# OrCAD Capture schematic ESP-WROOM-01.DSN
size A3; title: ESP-WROOM-01; rev: 1.0
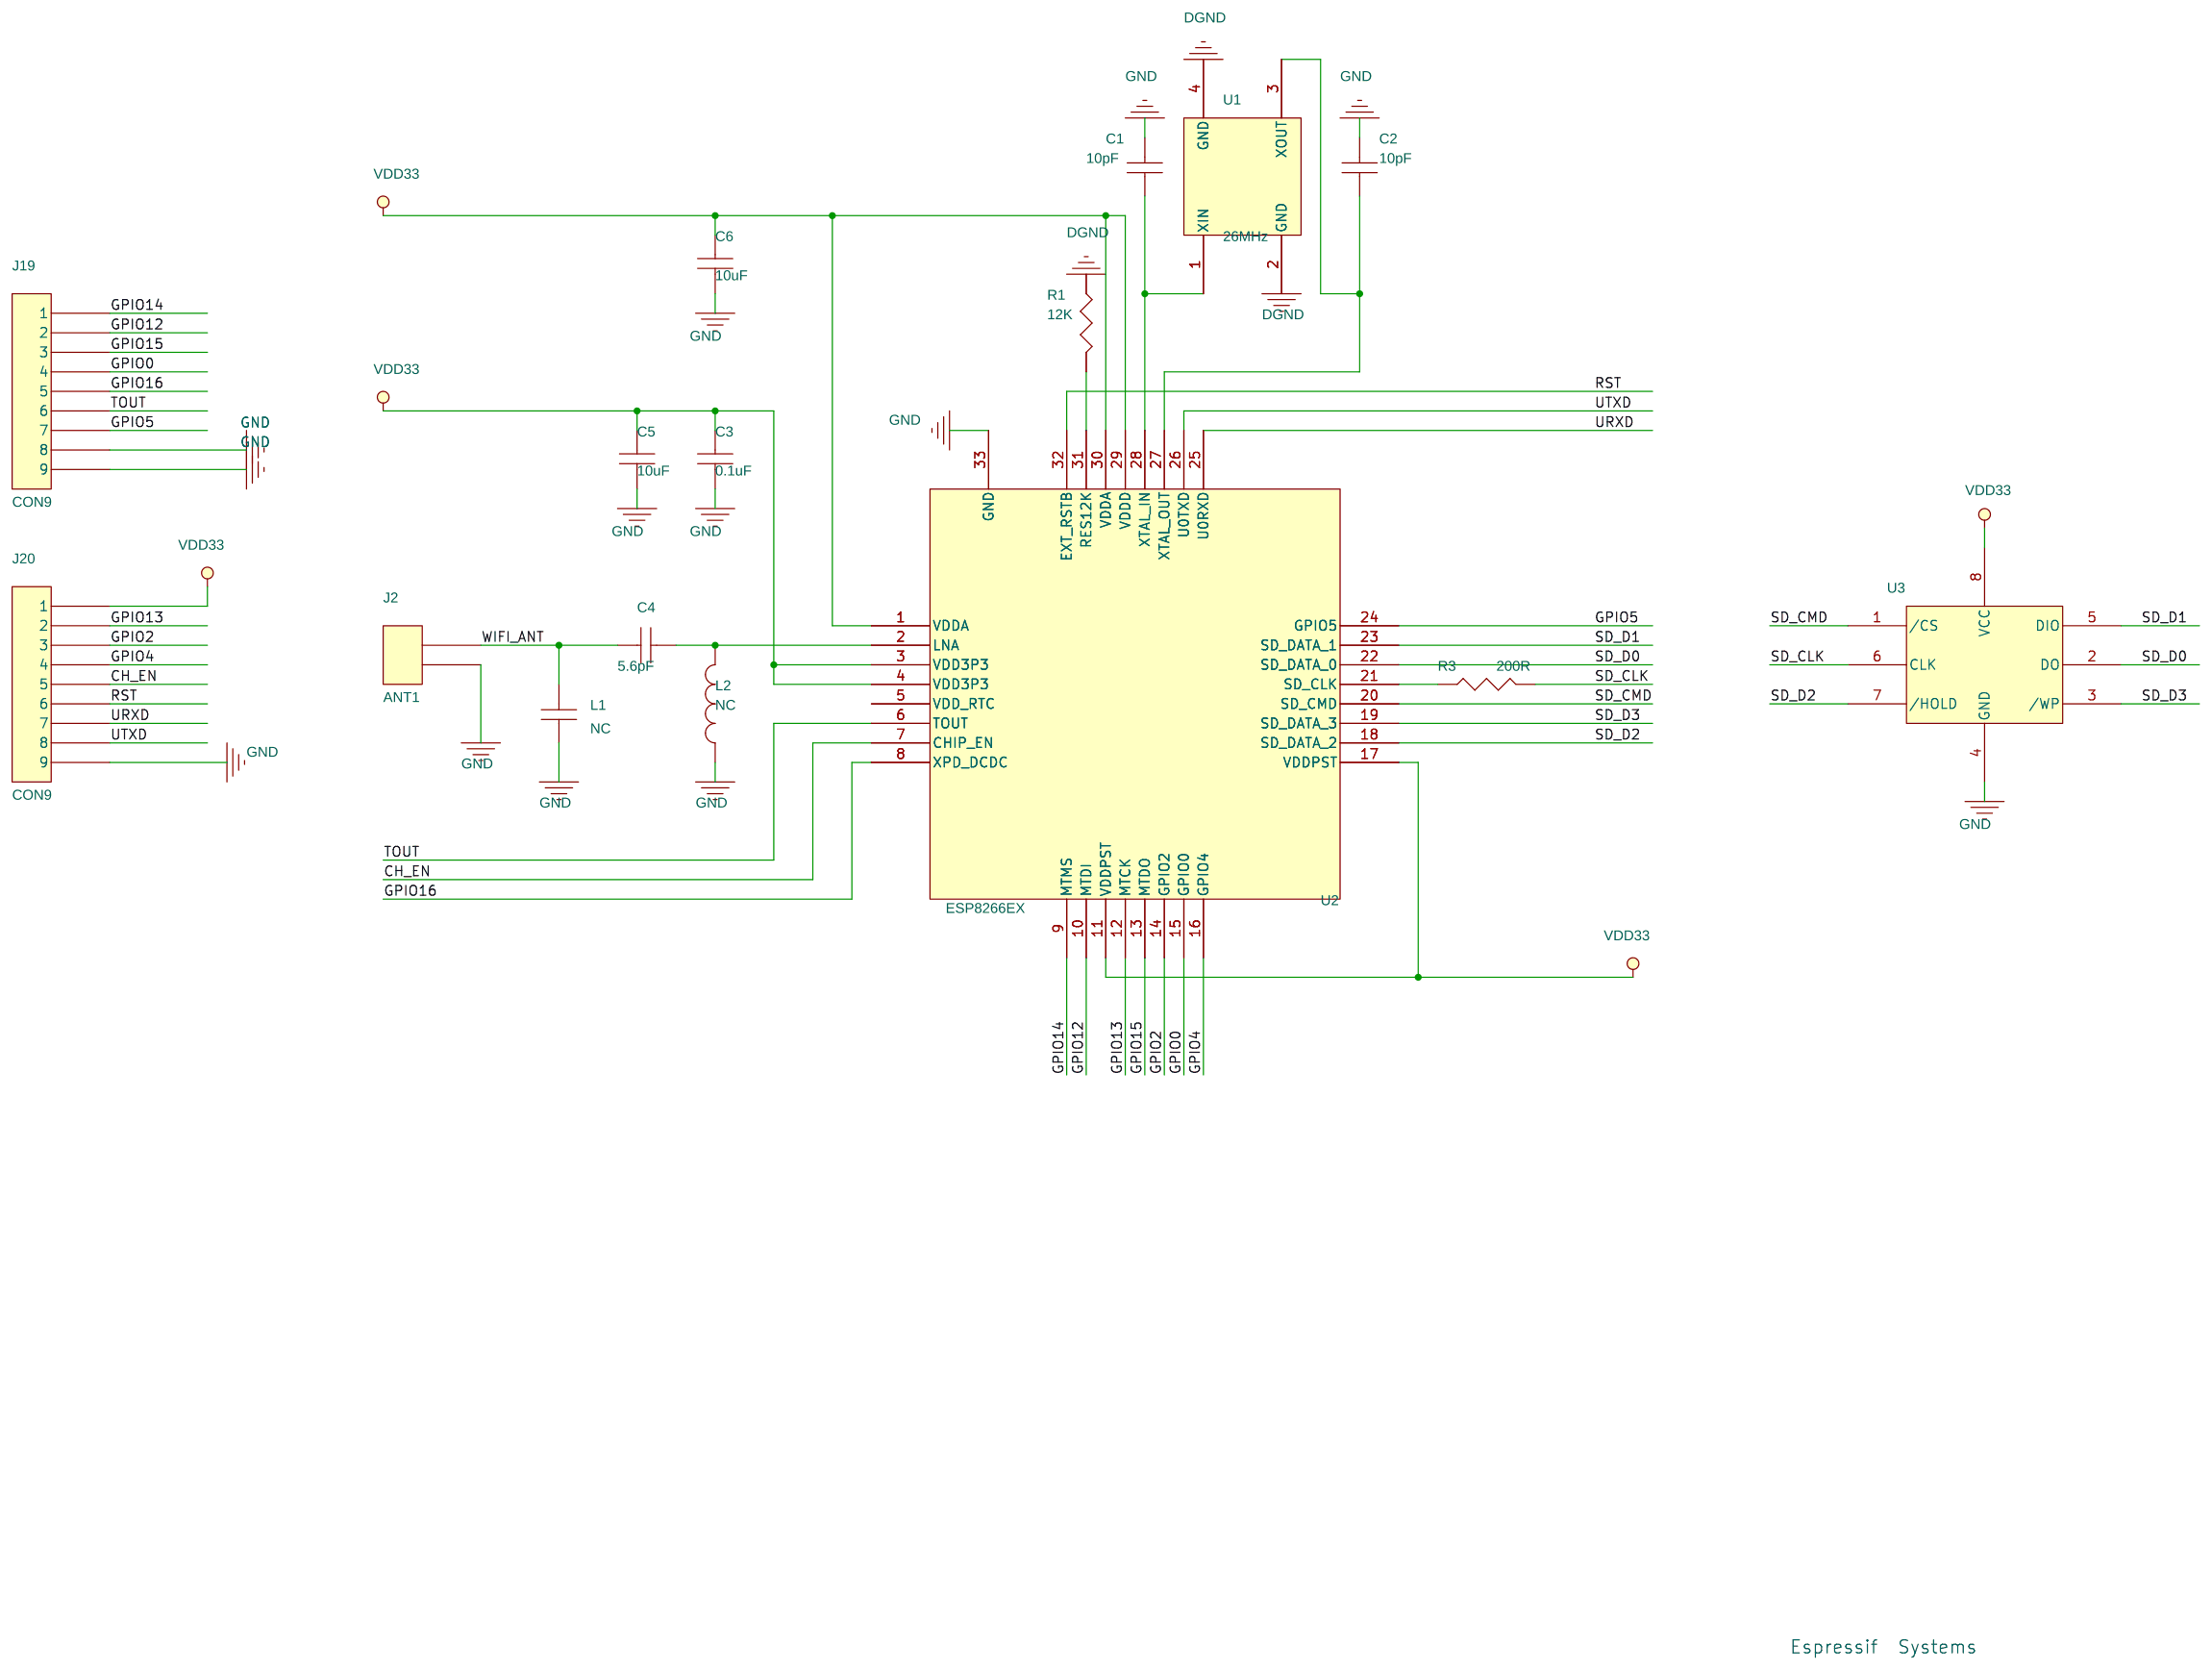
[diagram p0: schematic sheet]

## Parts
C1  10pF  [0402A]
C2  10pF  [0402A]
C3  0.1uF  [0402A]
C4  5.6pF  [0402A]
C5  10uF  [0603C]
C6  10uF  [0603C]
J2  ANT1  [ANT_DIP2]
J19  CON9  [CON9_2.0]
J20  CON9  [CON9_2.0]
L1  NC  [0402A]
L2  NC  [L0402//A]
R1  12K  [0402A]
R3  200R  [0402A]
U1  26MHz  [3225]
U2  ESP8266EX  [QFN32_3.7X3.7]
U3  FLASH  [SON-8N]

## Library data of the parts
C1-C6 L1 = CAP_NP
J2 = CON2
J19 = CON9
J20 = CON9_1
L2 = INDUCTOR
R1 R3 = RESISTOR
U1 = X1_0
U2 = ESP8080_1
U3 = FLASH_0

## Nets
GND: C1.2 C2.2 C3.2 C5.2 C6.2 J2.2 J19.8 J19.9 J20.9 L1.1 L2.1 R1.1 U1.2(GND) U1.4(GND) U2.33(GND) U3.4(GND)
VDD33: C3.1 C5.1 C6.1 J20.1 U2.1(VDDA) U2.3(VDD3P3) U2.4(VDD3P3) U2.11(VDDPST) U2.17(VDDPST) U2.29(VDDD) U2.30(VDDA) U3.8(VCC)
VDD_RTC: U2.5(VDD_RTC)
CH_EN: J20.5 U2.7(CHIP_EN)
GPIO0: J19.4 U2.15(GPIO0)
GPIO2: J20.3 U2.14(GPIO2)
GPIO4: J20.4 U2.16(GPIO4)
GPIO5: J19.7 U2.24(GPIO5)
GPIO12: J19.2 U2.10(MTDI)
GPIO13: J20.2 U2.12(MTCK)
GPIO14: J19.1 U2.9(MTMS)
GPIO15: J19.3 U2.13(MTDO)
GPIO16: J19.5 U2.8(XPD_DCDC)
RST: J20.6 U2.32(EXT_RSTB)
SD_CLK: R3.2 U3.6(CLK)
SD_CMD: U2.20(SD_CMD) U3.1(/CS)
SD_D0: U2.22(SD_DATA_0) U3.2(DO)
SD_D1: U2.23(SD_DATA_1) U3.5(DIO)
SD_D2: U2.18(SD_DATA_2) U3.7(/HOLD)
SD_D3: U2.19(SD_DATA_3) U3.3(/WP)
TOUT: J19.6 U2.6(TOUT)
URXD: J20.7 U2.25(U0RXD)
UTXD: J20.8 U2.26(U0TXD)
WIFI_ANT: C4.1 J2.1 L1.2
N5630608: C2.1 U1.3(XOUT) U2.27(XTAL_OUT)
N5630644: C4.2 L2.2 U2.2(LNA)
N5630726: C1.1 U1.1(XIN) U2.28(XTAL_IN)
N5630864: R1.2 U2.31(RES12K)
N5777066: R3.1 U2.21(SD_CLK)

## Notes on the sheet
- Espressif  Systems
